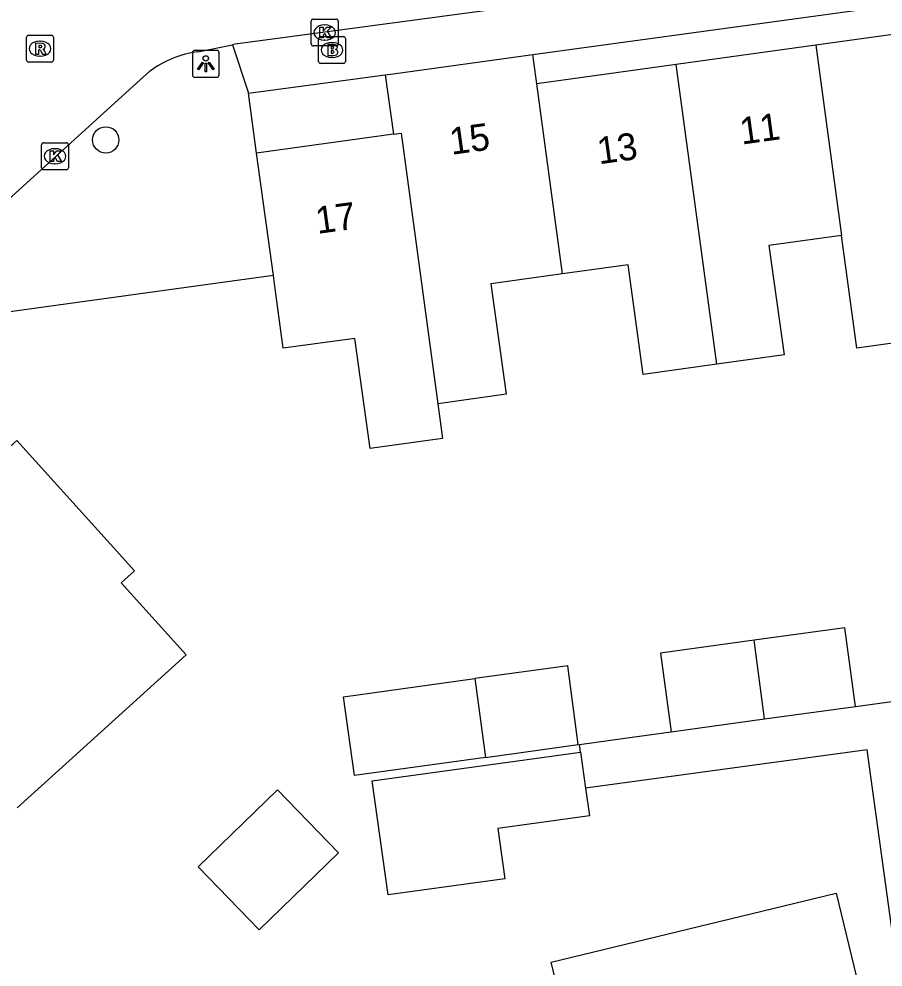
# Model space of a CAD drawing. Extents: x 163150 to 163546, y 380933 to 381635.
# Drawn here: x 163277.11 to 163309.19, y 381253.16 to 381288.37 of the extents above; entities that cross this region are included whole.
import ezdxf

# ---------------------------------------------------------------- set-up
doc = ezdxf.new("R2010")
doc.units = 0
for name, color, linetype in [('IMGEO_Boom', 7, 'Continuous'), ('IMGEO_Brandkraan', 7, 'Continuous'), ('IMGEO_Kolk', 7, 'Continuous'), ('IMGEO_Lichtpunt', 7, 'Continuous'), ('IMGEO_Pand', 7, 'Continuous'), ('IMGEO_Pand_nummerreeks', 7, 'Continuous'), ('IMGEO_Rijbaan_lokaal_open', 7, 'Continuous'), ('IMGEO_Rioolput', 7, 'Continuous'), ('IMGEO_Voetpad_open', 7, 'Continuous')]:
    doc.layers.add(name, color=color, linetype=linetype)

msp = doc.modelspace()

# ---------------------------------------------------------------- linework, layer by layer
at = {"layer": 'IMGEO_Boom'}
msp.add_circle((163280.328, 381283.875), 0.489, dxfattribs=at)
at = {"layer": 'IMGEO_Brandkraan'}
for p, q in [((163288.229, 381286.789), (163288.229, 381287.641)), ((163288.304, 381287.715), (163289.156, 381287.715)), ((163289.23, 381287.641), (163289.23, 381286.789)), ((163288.717, 381287.495), (163288.742, 381287.495)), ((163288.74, 381286.935), (163288.715, 381286.935)), ((163289.156, 381286.715), (163288.304, 381286.715))]:
    msp.add_line(p, q, dxfattribs=at)
for points in [[(163288.229, 381286.789), (163288.229, 381287.641)], [(163288.304, 381287.715), (163289.156, 381287.715)], [(163289.23, 381287.641), (163289.23, 381286.789)], [(163288.577, 381287.415), (163288.577, 381287.015), (163288.79, 381287.015)], [(163288.808, 381287.415), (163288.577, 381287.415)], [(163288.756, 381287.334), (163288.702, 381287.334), (163288.702, 381287.258)], [(163288.702, 381287.258), (163288.755, 381287.258)], [(163288.764, 381287.182), (163288.702, 381287.182), (163288.702, 381287.101)], [(163288.702, 381287.101), (163288.764, 381287.101)], [(163289.156, 381286.715), (163288.304, 381286.715)]]:
    msp.add_lwpolyline(points, dxfattribs=at)
for centre, radius, start, end in [((163288.306, 381287.639), 0.0765, 91.552, 178.448), ((163288.306, 381287.639), 0.0765, 91.552, 178.448), ((163289.154, 381287.639), 0.0765, 1.552, 88.448), ((163289.154, 381287.639), 0.0765, 1.552, 88.448), ((163288.757, 381287.296), 0.0379, 267.8285, 90.9355), ((163288.765, 381287.141), 0.0404, 269.8759, 90.5077), ((163288.812, 381287.27), 0.145, 59.4692, 91.5367), ((163288.837, 381287.317), 0.0922, 285.5137, 58.1501), ((163288.842, 381287.125), 0.105, 301.3115, 78.989), ((163288.796, 381287.266), 0.251, 268.6676, 293.5347), ((163288.306, 381286.791), 0.0765, 181.552, 268.448), ((163288.306, 381286.791), 0.0765, 181.552, 268.448), ((163289.154, 381286.791), 0.0765, 271.552, 358.448), ((163289.154, 381286.791), 0.0765, 271.552, 358.448)]:
    msp.add_arc(centre, radius, start, end, dxfattribs=at)
for centre, major_axis, ratio, start_param, end_param in [((163288.716, 381287.215), (-0.387, 0.002), 0.722429, 4.712389, 7.853982), ((163288.741, 381287.215), (-0.39, 0.002), 0.717154, 1.570796, 4.712389)]:
    msp.add_ellipse(centre, major_axis=major_axis, ratio=ratio, start_param=start_param, end_param=end_param, dxfattribs=at)
at = {"layer": 'IMGEO_Kolk'}
for p, q in [((163287.958, 381287.437), (163287.958, 381288.289)), ((163288.033, 381288.363), (163288.885, 381288.363)), ((163288.959, 381288.289), (163288.959, 381287.437)), ((163288.446, 381288.143), (163288.471, 381288.143)), ((163288.469, 381287.583), (163288.444, 381287.583)), ((163288.885, 381287.363), (163288.033, 381287.363)), ((163277.943, 381282.843), (163277.943, 381283.695)), ((163278.018, 381283.769), (163278.87, 381283.769)), ((163278.944, 381283.695), (163278.944, 381282.843)), ((163278.431, 381283.549), (163278.456, 381283.549)), ((163278.454, 381282.989), (163278.429, 381282.989)), ((163278.87, 381282.769), (163278.018, 381282.769))]:
    msp.add_line(p, q, dxfattribs=at)
for points in [[(163287.958, 381287.437), (163287.958, 381288.289)], [(163288.033, 381288.363), (163288.885, 381288.363)], [(163288.959, 381288.289), (163288.959, 381287.437)], [(163288.279, 381288.063), (163288.402, 381288.063), (163288.402, 381287.912), (163288.532, 381288.063), (163288.696, 381288.063), (163288.55, 381287.912), (163288.703, 381287.663), (163288.551, 381287.663), (163288.466, 381287.827), (163288.402, 381287.76), (163288.402, 381287.663), (163288.279, 381287.663), (163288.279, 381288.063)], [(163288.885, 381287.363), (163288.033, 381287.363)], [(163277.943, 381282.843), (163277.943, 381283.695)], [(163278.018, 381283.769), (163278.87, 381283.769)], [(163278.944, 381283.695), (163278.944, 381282.843)], [(163278.264, 381283.469), (163278.387, 381283.469), (163278.387, 381283.318), (163278.517, 381283.469), (163278.681, 381283.469), (163278.535, 381283.318), (163278.688, 381283.069), (163278.536, 381283.069), (163278.451, 381283.233), (163278.387, 381283.166), (163278.387, 381283.069), (163278.264, 381283.069), (163278.264, 381283.469)], [(163278.87, 381282.769), (163278.018, 381282.769)]]:
    msp.add_lwpolyline(points, dxfattribs=at)
for centre, start, end in [((163288.035, 381288.287), 91.552, 178.448), ((163288.035, 381288.287), 91.552, 178.448), ((163288.883, 381288.287), 1.552, 88.448), ((163288.883, 381288.287), 1.552, 88.448), ((163288.035, 381287.439), 181.552, 268.448), ((163288.035, 381287.439), 181.552, 268.448), ((163288.883, 381287.439), 271.552, 358.448), ((163288.883, 381287.439), 271.552, 358.448), ((163278.02, 381283.693), 91.552, 178.448), ((163278.02, 381283.693), 91.552, 178.448), ((163278.868, 381283.693), 1.552, 88.448), ((163278.868, 381283.693), 1.552, 88.448), ((163278.02, 381282.845), 181.552, 268.448), ((163278.02, 381282.845), 181.552, 268.448), ((163278.868, 381282.845), 271.552, 358.448), ((163278.868, 381282.845), 271.552, 358.448)]:
    msp.add_arc(centre, 0.0765, start, end, dxfattribs=at)
for centre, major_axis, ratio, start_param, end_param in [((163288.445, 381287.863), (-0.387, 0.002), 0.722429, 4.712389, 7.853982), ((163288.47, 381287.863), (-0.39, 0.002), 0.717154, 1.570796, 4.712389), ((163278.43, 381283.269), (-0.387, 0.002), 0.722429, 4.712389, 7.853982), ((163278.455, 381283.269), (-0.39, 0.002), 0.717154, 1.570796, 4.712389)]:
    msp.add_ellipse(centre, major_axis=major_axis, ratio=ratio, start_param=start_param, end_param=end_param, dxfattribs=at)
at = {"layer": 'IMGEO_Lichtpunt'}
for p, q in [((163284.446, 381287.199), (163283.638, 381287.199)), ((163284.446, 381287.199), (163283.638, 381287.199)), ((163283.544, 381287.104), (163283.544, 381286.297)), ((163283.544, 381287.104), (163283.544, 381286.297)), ((163284.54, 381286.297), (163284.54, 381287.104)), ((163284.54, 381286.297), (163284.54, 381287.104)), ((163283.638, 381286.203), (163284.446, 381286.203)), ((163283.638, 381286.203), (163284.446, 381286.203))]:
    msp.add_line(p, q, dxfattribs=at)
for points in [[(163283.918, 381286.768), (163283.957, 381286.74), (163283.769, 381286.478), (163283.731, 381286.505), (163283.918, 381286.768)], [(163284.02, 381286.72), (163284.067, 381286.72), (163284.067, 381286.398), (163284.02, 381286.398), (163284.02, 381286.72)], [(163284.13, 381286.74), (163284.168, 381286.767), (163284.355, 381286.505), (163284.316, 381286.477), (163284.13, 381286.74)]]:
    msp.add_lwpolyline(points, dxfattribs=at)
msp.add_circle((163284.043, 381286.902), 0.0994, dxfattribs=at)
for centre, start, end in [((163283.638, 381287.104), 90, 180), ((163283.638, 381287.104), 90, 180), ((163284.446, 381287.104), 0, 90), ((163284.446, 381287.104), 0, 90), ((163283.638, 381286.297), 180, 270), ((163283.638, 381286.297), 180, 270), ((163284.446, 381286.297), 270, 0), ((163284.446, 381286.297), 270, 360)]:
    msp.add_arc(centre, 0.0946, start, end, dxfattribs=at)
at = {"layer": 'IMGEO_Pand'}
for points in [[(163311.878, 381288.109), (163306.696, 381287.392)], [(163306.696, 381287.392), (163301.514, 381286.675)], [(163306.696, 381287.392), (163307.649, 381280.326)], [(163290.704, 381286.291), (163291.005, 381286.333), (163296.185, 381287.049)], [(163296.335, 381285.959), (163296.185, 381287.049)], [(163301.514, 381286.675), (163296.335, 381285.959)], [(163303.016, 381275.546), (163301.514, 381286.675)], [(163290.704, 381286.291), (163291.01, 381284.084)], [(163297.285, 381278.902), (163296.335, 381285.959)], [(163291.01, 381284.084), (163285.926, 381283.381)], [(163291.01, 381284.084), (163291.303, 381284.125), (163292.658, 381274.078)], [(163286.554, 381278.836), (163285.926, 381283.381)], [(163307.649, 381280.326), (163304.953, 381279.953), (163305.514, 381275.891), (163303.016, 381275.546)], [(163313.396, 381276.854), (163310.708, 381276.482), (163308.214, 381276.137), (163307.649, 381280.326)], [(163303.016, 381275.546), (163300.285, 381275.168), (163299.722, 381279.239), (163297.285, 381278.902)], [(163292.658, 381274.078), (163292.832, 381272.79), (163290.147, 381272.418), (163289.582, 381276.503), (163286.921, 381276.136), (163286.609, 381278.441), (163286.554, 381278.836)], [(163297.285, 381278.902), (163294.624, 381278.534), (163295.192, 381274.427), (163292.843, 381274.103), (163292.658, 381274.078)], [(163269.002, 381268.232), (163273.224, 381272.045), (163274.601, 381270.52), (163277.026, 381272.71), (163280.377, 381268.999), (163281.39, 381267.876), (163280.896, 381267.43), (163283.318, 381264.748), (163279.109, 381260.944), (163277.04, 381259.074)], [(163308.161, 381262.837), (163307.767, 381265.761), (163304.399, 381265.297)], [(163304.399, 381265.297), (163300.926, 381264.818), (163301.319, 381261.894)], [(163304.794, 381262.373), (163304.399, 381265.297)], [(163294.43, 381260.944), (163297.874, 381261.419), (163297.481, 381264.343), (163294.036, 381263.868)], [(163294.43, 381260.944), (163289.562, 381260.273), (163289.159, 381263.195), (163290.225, 381263.342), (163294.036, 381263.868)], [(163294.036, 381263.868), (163294.43, 381260.944)], [(163304.794, 381262.373), (163308.161, 381262.837)], [(163301.319, 381261.894), (163304.794, 381262.373)], [(163298.145, 381259.806), (163298.288, 381258.774), (163294.892, 381258.305), (163295.15, 381256.437), (163290.81, 381255.838), (163290.226, 381260.071), (163297.961, 381261.138)], [(163297.961, 381261.138), (163298.145, 381259.806)], [(163288.971, 381257.404), (163286.023, 381254.546), (163283.761, 381256.879), (163286.709, 381259.737), (163288.971, 381257.404)], [(163307.445, 381255.9), (163308.483, 381251.605), (163297.911, 381249.049), (163296.872, 381253.344), (163307.445, 381255.9)]]:
    msp.add_lwpolyline(points, dxfattribs=at)
at = {"layer": 'IMGEO_Rijbaan_lokaal_open'}
for points in [[(163329.119, 381293.327), (163285.136, 381287.427), (163285.037, 381287.407)], [(163283.753, 381287.147), (163285.037, 381287.407)], [(163276.429, 381281.397), (163281.482, 381285.994), (163281.963, 381286.424)]]:
    msp.add_lwpolyline(points, dxfattribs=at)
msp.add_arc((163284.234, 381283.379), 3.798, 97.2723, 126.7163, dxfattribs=at)
at = {"layer": 'IMGEO_Rioolput'}
for p, q in [((163277.387, 381286.837), (163277.387, 381287.689)), ((163277.462, 381287.763), (163278.314, 381287.763)), ((163277.875, 381287.543), (163277.9, 381287.543)), ((163278.388, 381287.689), (163278.388, 381286.837)), ((163277.898, 381286.983), (163277.873, 381286.983)), ((163278.314, 381286.763), (163277.462, 381286.763))]:
    msp.add_line(p, q, dxfattribs=at)
for points in [[(163277.387, 381286.837), (163277.387, 381287.689)], [(163277.462, 381287.763), (163278.314, 381287.763)], [(163278.388, 381287.689), (163278.388, 381286.837)], [(163277.976, 381287.461), (163277.724, 381287.463), (163277.724, 381287.063)], [(163277.724, 381287.063), (163277.848, 381287.063), (163277.848, 381287.225), (163277.859, 381287.225)], [(163277.902, 381287.382), (163277.848, 381287.382), (163277.848, 381287.301)], [(163277.848, 381287.301), (163277.9, 381287.301)], [(163277.906, 381287.196), (163277.977, 381287.063), (163278.117, 381287.063), (163278.052, 381287.189)], [(163278.314, 381286.763), (163277.462, 381286.763)]]:
    msp.add_lwpolyline(points, dxfattribs=at)
for centre, radius, start, end in [((163277.464, 381287.687), 0.0765, 91.552, 178.448), ((163277.464, 381287.687), 0.0765, 91.552, 178.448), ((163278.312, 381287.687), 0.0765, 1.552, 88.448), ((163278.312, 381287.687), 0.0765, 1.552, 88.448), ((163277.858, 381287.172), 0.0533, 26.0293, 88.6989), ((163277.884, 381287.49), 0.19, 274.7715, 282.9687), ((163277.908, 381287.286), 0.0964, 77.0061, 93.1865), ((163277.922, 381287.343), 0.0378, 276.6634, 79.6772), ((163277.975, 381287.351), 0.109, 350.3612, 89.416), ((163277.973, 381287.351), 0.112, 277.5842, 350.9817), ((163277.957, 381287.136), 0.108, 29.5134, 73.7905), ((163277.464, 381286.839), 0.0765, 181.552, 268.448), ((163277.464, 381286.839), 0.0765, 181.552, 268.448), ((163278.312, 381286.839), 0.0765, 271.552, 358.448), ((163278.312, 381286.839), 0.0765, 271.552, 358.448)]:
    msp.add_arc(centre, radius, start, end, dxfattribs=at)
for centre, major_axis, ratio, start_param, end_param in [((163277.874, 381287.263), (-0.387, 0.002), 0.722429, 4.712389, 7.853982), ((163277.899, 381287.263), (-0.39, 0.002), 0.717154, 1.570796, 4.712389)]:
    msp.add_ellipse(centre, major_axis=major_axis, ratio=ratio, start_param=start_param, end_param=end_param, dxfattribs=at)
at = {"layer": 'IMGEO_Voetpad_open'}
for points in [[(163296.185, 381287.049), (163322.095, 381290.605)], [(163285.037, 381287.407), (163285.634, 381285.611)], [(163285.634, 381285.611), (163290.704, 381286.291)], [(163285.926, 381283.381), (163285.634, 381285.611)], [(163286.554, 381278.836), (163284.028, 381278.488), (163275.144, 381277.265), (163274.301, 381277.041), (163273.554, 381276.589), (163260.303, 381264.494), (163260.154, 381264.566), (163247.371, 381253.054)], [(163308.161, 381262.837), (163309.974, 381263.087)], [(163297.961, 381261.138), (163297.913, 381261.424), (163299.606, 381261.658), (163301.319, 381261.894)], [(163286.908, 381247.77), (163287.555, 381248.354), (163289.781, 381249.639), (163311.555, 381199.092), (163317.049, 381199.939), (163308.6, 381261.231), (163298.145, 381259.806)]]:
    msp.add_lwpolyline(points, dxfattribs=at)

# ---------------------------------------------------------------- texts
at = {"layer": 'IMGEO_Pand_nummerreeks'}
for s, rotation, p in [('11', 7.8742, (163303.941, 381283.7)), ('15', 7.8724, (163293.166, 381283.32)), ('13', 7.8742, (163298.647, 381282.968)), ('17', 7.8724, (163288.189, 381280.383))]:
    msp.add_text(s, height=1, rotation=rotation, dxfattribs=at).set_placement(p)

doc.saveas('drawing.dxf')
